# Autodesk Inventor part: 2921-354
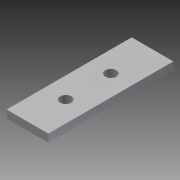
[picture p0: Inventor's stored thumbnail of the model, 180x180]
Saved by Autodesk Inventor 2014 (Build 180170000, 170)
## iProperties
Company: NHTSA/VRTC
Created: 2012-12
Part Number: 2921-354
Material: Steel, Mild
Document SubType Name: Modeling
Designer: Mike Vanvoorhis
Density: 7.86 g/cm^3
Mass: 558.198 g
Surface Area: 195.903 cm^2
Volume: 71.0175 cm^3
Project: CHILD SIDE IMPACT SLED
Description: LOWER ANCHOR LOWER ATTACHMENT PLATE
Appearance: Steel
Stock Number: BAR 50.8 (2") x 9.5 (3/8") x 152.4 (6")
Author: Dave walker
Title: Lowwer Anchor Lower Attachment Plate
Subject: Child Side Impact Sled
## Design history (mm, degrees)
sketch "Sketch1"
  geometry: L1 (0, 0)-(50.8, 0); L2 (50.8, 0)-(50.8, 9.525); L3 (50.8, 9.525)-(0, 9.525); L4 (0, 9.525)-(0, 0)
  constraints: 8 end point, 2 parallel, 1 horizontal, 1 perpendicular
  dimensions: "d0" = 50.8 distance of L3.end L2.end; "d1" = 9.525 distance of L2.end L1.end
extrude "Extrusion1" new body sketch "Sketch1" distance "d2" = 152.4; taper "d3" = 0 deg
sketch "Sketch2"
  geometry: L1 (50.8, 152.4)-(0, 152.4) reference; L2 (50.8, 0)-(50.8, 152.4) reference; L3 (25.4, 152.4)-(25.4, 101.6); L4 (25.4, 101.6)-(25.4, 46.6)
  constraints: 4 end point, 1 collinear, 1 midpoint, 1 parallel
  dimensions: "d4" = 50.8 distance of L3.start L3.end; "d5" = 55 distance of L3.end L4.end
hole "Hole1" sketch "Sketch2" at (25.4, 101.6), (25.4, 46.6) diameter "d6" = 13.5; stored, may be unused: countersink angle "d10" = 82 deg, drill point angle "d12" = 118 deg; dims "d7" = 19.05, "d8" = 9.525, "d9" = 6.35, "d11" = 25.4
body "Solid1"
